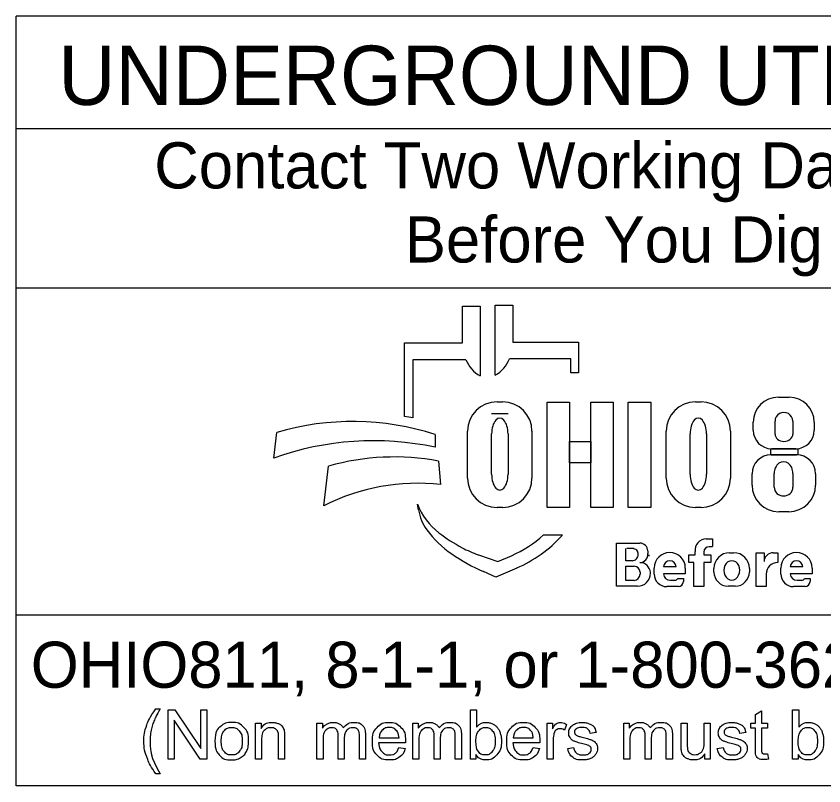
# Model space of a CAD drawing. Extents: x 0 to 34, y 0 to 22.
# Drawn here: x 3.363 to 5.816, y 2.547 to 4.885 of the extents above; entities that cross this region are included whole.
import ezdxf

# ---------------------------------------------------------------- set-up
doc = ezdxf.new("R2010")
doc.units = 0
doc.layers.add('SH_Data', color=7, linetype='Continuous')
doc.layers.add('SH_Text', color=7, linetype='Continuous')

msp = doc.modelspace()

# ---------------------------------------------------------------- linework, layer by layer
at = {"layer": 'SH_Data'}
for p, q in [((3.3626, 2.5473), (3.3626, 4.8848)), ((7.6126, 4.8848), (3.3626, 4.8848)), ((3.3626, 4.5433), (7.6126, 4.5433)), ((3.3626, 4.0599), (7.6126, 4.0599)), ((7.6126, 3.0652), (3.3626, 3.0652)), ((7.6126, 2.5473), (3.3626, 2.5473))]:
    msp.add_line(p, q, dxfattribs=at)
at = {"layer": 'SH_Text'}
for p, q in [((4.7186, 3.8928), (4.7186, 4.0043)), ((4.7186, 4.0043), (4.7723, 4.0043)), ((4.7723, 4.0043), (4.7723, 3.7923)), ((4.8179, 3.7946), (4.8179, 4.0067)), ((4.8179, 4.0067), (4.8716, 4.0067)), ((4.8716, 4.0067), (4.8716, 3.8952)), ((4.5427, 3.669), (4.5427, 3.8928)), ((4.5427, 3.8928), (4.7186, 3.8928)), ((4.8716, 3.8952), (5.0708, 3.8952)), ((5.0708, 3.8952), (5.0708, 3.8014)), ((4.5679, 3.8414), (4.5679, 3.6646)), ((4.729, 3.8414), (4.5679, 3.8414)), ((5.0475, 3.8437), (4.8612, 3.8437)), ((5.0475, 3.8014), (5.0475, 3.8437)), ((5.0708, 3.8014), (5.0475, 3.8014)), ((4.8236, 3.7137), (4.8402, 3.7137)), ((5.4267, 3.7137), (5.4432, 3.7137)), ((5.6782, 3.7277), (5.7109, 3.7277)), ((4.8569, 3.6767), (4.8071, 3.6767)), ((5.6019, 3.6271), (5.6019, 3.6514)), ((5.668, 3.6157), (5.668, 3.655)), ((5.7222, 3.655), (5.7222, 3.6157)), ((5.7872, 3.6514), (5.7872, 3.6271)), ((4.1453, 3.5427), (4.1547, 3.6208)), ((4.636, 3.6143), (4.636, 3.5755)), ((4.7342, 3.4822), (4.7342, 3.6242)), ((4.8071, 3.4936), (4.8071, 3.6159)), ((4.8569, 3.6159), (4.8569, 3.4936)), ((4.9296, 3.6242), (4.9296, 3.4822)), ((5.3372, 3.4822), (5.3372, 3.6242)), ((5.4101, 3.4936), (5.4101, 3.6159)), ((5.4599, 3.6159), (5.4599, 3.4936)), ((5.5327, 3.6242), (5.5327, 3.4822)), ((5.7312, 3.5711), (5.6579, 3.5711)), ((4.6459, 3.5337), (4.6522, 3.4627)), ((5.6561, 3.5527), (5.7334, 3.5527)), ((4.2971, 3.3981), (4.3118, 3.5183)), ((5.5982, 3.4608), (5.5982, 3.4949)), ((5.6657, 3.4549), (5.6657, 3.4958)), ((5.7225, 3.4958), (5.7225, 3.4549)), ((5.7913, 3.4949), (5.7913, 3.4608)), ((4.5848, 3.3852), (4.5818, 3.4031)), ((4.8402, 3.3927), (4.8236, 3.3927)), ((5.4432, 3.3927), (5.4267, 3.3927)), ((5.7103, 3.3799), (5.6791, 3.3799)), ((4.9651, 3.3093), (5.0225, 3.3093)), ((5.459, 3.2971), (5.4784, 3.2971)), ((5.4784, 3.2971), (5.4784, 3.2741)), ((5.1864, 3.1536), (5.1864, 3.2843)), ((5.1864, 3.2843), (5.2576, 3.2843)), ((5.2144, 3.2308), (5.2144, 3.2678)), ((5.2396, 3.2678), (5.2183, 3.2678)), ((5.4784, 3.2736), (5.4683, 3.2736)), ((4.7667, 3.249), (4.8261, 3.2285)), ((4.8261, 3.2285), (4.8671, 3.2463)), ((5.2813, 3.2606), (5.2813, 3.2527)), ((5.4064, 3.2257), (5.4064, 3.2487)), ((5.4064, 3.2487), (5.4257, 3.2487)), ((5.4257, 3.2487), (5.4257, 3.2592)), ((5.4518, 3.2572), (5.4518, 3.2487)), ((5.4518, 3.2487), (5.4734, 3.2487)), ((5.4734, 3.2487), (5.4734, 3.2257)), ((5.5302, 3.2553), (5.5423, 3.2553)), ((5.6105, 3.1524), (5.6105, 3.2551)), ((5.6105, 3.2551), (5.635, 3.2551)), ((5.635, 3.2551), (5.635, 3.2282)), ((5.6623, 3.2551), (5.6761, 3.2551)), ((5.6761, 3.2551), (5.6761, 3.2254)), ((5.2338, 3.2308), (5.2144, 3.2308)), ((5.4213, 3.2257), (5.4064, 3.2257)), ((5.4213, 3.1524), (5.4213, 3.2257)), ((5.4734, 3.2257), (5.4518, 3.2257)), ((5.4518, 3.2257), (5.4518, 3.1524)), ((4.8201, 3.1815), (4.7827, 3.1979)), ((4.8834, 3.2089), (4.8201, 3.1815)), ((5.2144, 3.1714), (5.2144, 3.2143)), ((5.2144, 3.2143), (5.2399, 3.2143)), ((5.258, 3.1962), (5.258, 3.1898)), ((5.2894, 3.1933), (5.2894, 3.1929)), ((5.301, 3.1904), (5.301, 3.2088)), ((5.3675, 3.2128), (5.329, 3.2128)), ((5.3955, 3.1911), (5.3291, 3.1911)), ((5.3955, 3.2088), (5.3955, 3.1911)), ((5.4824, 3.1967), (5.4824, 3.2075)), ((5.5902, 3.2075), (5.5902, 3.1967)), ((5.641, 3.1905), (5.641, 3.1524)), ((5.6859, 3.1904), (5.6859, 3.2088)), ((5.7525, 3.2128), (5.7139, 3.2128)), ((5.7804, 3.1911), (5.714, 3.1911)), ((5.7804, 3.2088), (5.7804, 3.1911)), ((5.2397, 3.1714), (5.2144, 3.1714)), ((5.35, 3.1719), (5.3641, 3.1719)), ((5.3727, 3.1774), (5.3895, 3.1774)), ((5.3895, 3.1774), (5.3895, 3.1676)), ((5.7349, 3.1719), (5.749, 3.1719)), ((5.7576, 3.1774), (5.7745, 3.1774)), ((5.7745, 3.1774), (5.7745, 3.1676)), ((5.2501, 3.1536), (5.1864, 3.1536)), ((5.3743, 3.1524), (5.3389, 3.1524)), ((5.4518, 3.1524), (5.4213, 3.1524)), ((5.5474, 3.1539), (5.5252, 3.1539)), ((5.641, 3.1524), (5.6105, 3.1524)), ((5.7592, 3.1524), (5.7238, 3.1524))]:
    msp.add_line(p, q, dxfattribs=at)
for points in [[(4.9761, 3.7126), (5.044, 3.7126), (5.044, 3.3926), (4.9761, 3.3926)], [(5.1082, 3.7126), (5.1762, 3.7126), (5.1762, 3.3926), (5.1082, 3.3926)], [(5.2215, 3.7126), (5.2903, 3.7126), (5.2903, 3.3926), (5.2215, 3.3926)], [(5.044, 3.5927), (5.1082, 3.5927), (5.1082, 3.5287), (5.044, 3.5287)], [(5.6557, 3.5711), (5.7374, 3.5711), (5.7374, 3.5526), (5.6557, 3.5526)]]:
    msp.add_lwpolyline(points, close=True, dxfattribs=at)
for points in [[(3.7872, 2.7811), (3.8004, 2.7811)], [(3.824, 2.6285), (3.824, 2.7786), (3.8443, 2.7786), (3.9233, 2.6607), (3.9233, 2.7786), (3.9423, 2.7786), (3.9423, 2.6285), (3.922, 2.6285), (3.843, 2.7464), (3.843, 2.6285), (3.824, 2.6285)], [(4.7594, 2.6285), (4.7424, 2.6285), (4.7424, 2.7786), (4.7608, 2.7786), (4.7608, 2.7251)], [(5.6084, 2.6603), (5.6084, 2.723), (5.5947, 2.723), (5.5947, 2.7373), (5.6084, 2.7373), (5.6084, 2.7642), (5.6268, 2.7753), (5.6268, 2.7373), (5.6452, 2.7373), (5.6452, 2.723), (5.6268, 2.723), (5.6268, 2.6592)], [(5.7385, 2.6285), (5.7214, 2.6285), (5.7214, 2.7786), (5.7399, 2.7786), (5.7399, 2.7251)], [(4.0899, 2.6285), (4.0899, 2.7373), (4.1065, 2.7373), (4.1065, 2.7218)], [(4.2763, 2.6285), (4.2763, 2.7373), (4.2928, 2.7373), (4.2928, 2.722)], [(4.5677, 2.6285), (4.5677, 2.7373), (4.5842, 2.7373), (4.5842, 2.722)], [(4.9755, 2.6285), (4.9755, 2.7373), (4.9921, 2.7373), (4.9921, 2.7208)], [(5.0345, 2.7338), (5.0281, 2.7168)], [(5.2087, 2.6285), (5.2087, 2.7373), (5.2252, 2.7373), (5.2252, 2.722)], [(5.383, 2.6699), (5.383, 2.7373), (5.4014, 2.7373), (5.4014, 2.677)], [(5.4527, 2.679), (5.4527, 2.7373), (5.4711, 2.7373), (5.4711, 2.6285), (5.4547, 2.6285)], [(4.4239, 2.7031), (4.4239, 2.6285), (4.4054, 2.6285), (4.4054, 2.697)], [(4.7152, 2.7031), (4.7152, 2.6285), (4.6968, 2.6285), (4.6968, 2.697)], [(5.1245, 2.7092), (5.1064, 2.7068)], [(5.3562, 2.7031), (5.3562, 2.6285), (5.3378, 2.6285), (5.3378, 2.697)], [(5.5791, 2.7092), (5.561, 2.7068)], [(4.1084, 2.6879), (4.1084, 2.6285), (4.0899, 2.6285)], [(4.1783, 2.6954), (4.1783, 2.6285), (4.1599, 2.6285), (4.1599, 2.6946)], [(4.2948, 2.6849), (4.2948, 2.6285), (4.2763, 2.6285)], [(4.3594, 2.6916), (4.3594, 2.6285), (4.341, 2.6285), (4.341, 2.6991)], [(4.5451, 2.6781), (4.4639, 2.6781)], [(4.465, 2.6932), (4.5257, 2.6932)], [(4.5861, 2.6849), (4.5861, 2.6285), (4.5677, 2.6285)], [(4.6508, 2.6916), (4.6508, 2.6285), (4.6324, 2.6285), (4.6324, 2.6991)], [(4.9531, 2.6781), (4.8719, 2.6781)], [(4.8729, 2.6932), (4.9337, 2.6932)], [(4.9939, 2.6855), (4.9939, 2.6285), (4.9755, 2.6285)], [(5.2271, 2.6849), (5.2271, 2.6285), (5.2087, 2.6285)], [(5.2918, 2.6916), (5.2918, 2.6285), (5.2734, 2.6285), (5.2734, 2.6991)], [(4.5255, 2.6636), (4.5446, 2.6612)], [(4.9335, 2.6636), (4.9526, 2.6612)], [(5.0381, 2.661), (5.0563, 2.6638)], [(5.4927, 2.661), (5.5109, 2.6638)], [(4.7594, 2.6421), (4.7594, 2.6285)], [(5.4547, 2.6285), (5.4547, 2.6445)], [(5.6452, 2.6449), (5.6478, 2.6286)], [(5.7385, 2.6421), (5.7385, 2.6285)], [(3.8004, 2.5843), (3.7872, 2.5843)]]:
    msp.add_lwpolyline(points, dxfattribs=at)
for centre, radius, start, end in [((4.8204, 3.8782), 0.0985, 201.9296, 240.7469), ((4.7698, 3.8805), 0.0985, 299.2531, 338.0704), ((4.8236, 3.6242), 0.0895, 90, 180), ((4.8402, 3.6242), 0.0895, 0, 90), ((5.4267, 3.6242), 0.0895, 90, 180), ((5.4432, 3.6242), 0.0895, 0, 90), ((5.6782, 3.6514), 0.0763, 90, 180), ((5.7109, 3.6514), 0.0763, 0, 90), ((4.4145, 2.86), 0.8191, 79.2074, 81.0007), ((4.3848, 2.8347), 0.8191, 72.1402, 106.3144), ((5.6579, 3.6271), 0.056, 180, 270), ((5.7312, 3.6271), 0.056, 270, 0), ((4.4478, 2.7036), 0.8919, 77.8238, 109.8274), ((4.5118, 2.8139), 0.7322, 79.44, 105.8467), ((5.6561, 3.4949), 0.0579, 90, 180), ((5.7334, 3.4949), 0.0579, 0, 90), ((4.5838, 2.8307), 0.6357, 83.8248, 116.8021), ((4.8236, 3.4822), 0.0895, 180, 270), ((4.8402, 3.4822), 0.0895, 270, 0), ((5.4267, 3.4822), 0.0895, 180, 270), ((5.4432, 3.4822), 0.0895, 270, 0), ((5.6791, 3.4608), 0.081, 180, 270), ((5.7103, 3.4608), 0.081, 270, 0), ((4.7692, 3.4753), 0.2008, 201.0457, 232.5314), ((4.7261, 3.4093), 0.1433, 189.6817, 216.0884), ((4.8598, 3.5068), 0.3088, 216.0884, 235.7167), ((4.9617, 3.7265), 0.5173, 232.5314, 241.794), ((4.7237, 3.5768), 0.3602, 293.4582, 312.0712), ((4.7237, 3.5768), 0.401, 293.4582, 317.8286), ((5.459, 3.2636), 0.0335, 90, 187.5187), ((4.8765, 3.5677), 0.3371, 241.794, 250.9821), ((5.2356, 3.2509), 0.0169, 357.8325, 90), ((5.2576, 3.2606), 0.0238, 0, 90), ((5.4683, 3.2572), 0.0165, 90, 180), ((5.0263, 3.751), 0.6044, 235.7167, 246.2325), ((5.2338, 3.2496), 0.0187, 270, 2.0582), ((5.2572, 3.2498), 0.0243, 270, 6.6529), ((5.2678, 3.2484), 0.0175, 347.4023, 0), ((5.3482, 3.2088), 0.0473, 0, 180), ((5.5302, 3.2075), 0.0478, 90, 180), ((5.5423, 3.2075), 0.0478, 0, 90), ((5.6619, 3.2282), 0.0269, 89.2449, 180), ((5.7331, 3.2088), 0.0473, 0, 180), ((5.2573, 3.1934), 0.0321, 4.0748, 90), ((5.3483, 3.2118), 0.0193, 2.9632, 177.0368), ((5.6759, 3.1905), 0.0349, 89.6033, 180), ((5.7332, 3.2118), 0.0193, 2.9632, 177.0368), ((5.2399, 3.1962), 0.0181, 0, 90), ((5.2501, 3.1929), 0.0393, 270, 0), ((5.2564, 3.1933), 0.033, 0, 11.7502), ((5.3389, 3.1904), 0.038, 180, 270), ((5.35, 3.1929), 0.021, 184.827, 270), ((5.5252, 3.1967), 0.0428, 180, 270), ((5.5474, 3.1967), 0.0428, 270, 0), ((5.7238, 3.1904), 0.038, 180, 270), ((5.7349, 3.1929), 0.021, 184.827, 270), ((5.2397, 3.1898), 0.0184, 270, 0), ((5.3641, 3.1813), 0.00938, 270, 335.9979), ((5.3743, 3.1676), 0.0152, 270, 0), ((5.749, 3.1813), 0.00938, 270, 335.9979), ((5.7592, 3.1676), 0.0152, 270, 0)]:
    msp.add_arc(centre, radius, start, end, dxfattribs=at)
for centre, major_axis, ratio, start_param, end_param in [((5.6951, 3.655), (0.0271, 0), 0.969373, 0, 3.141593), ((4.832, 3.6159), (0, 0.0484), 0.514403, 4.712389, 7.853982), ((5.435, 3.6159), (0, 0.0484), 0.514403, 4.712389, 7.853982), ((5.6951, 3.6157), (0.0271, 0), 0.818453, 3.141593, 6.283185), ((5.6941, 3.4958), (0, 0.0358), 0.794529, 4.712389, 7.853982), ((4.832, 3.4936), (0, 0.0484), 0.514403, 1.570796, 4.712389), ((5.435, 3.4936), (0, 0.0484), 0.514403, 1.570796, 4.712389), ((5.6941, 3.4549), (0.0284, 0), 0.959837, 3.141593, 6.283185), ((5.5367, 3.2021), (0, 0.029), 0.832186, 4.712389, 7.853982), ((5.5367, 3.2021), (0, 0.0302), 0.797287, 1.570796, 4.712389)]:
    msp.add_ellipse(centre, major_axis=major_axis, ratio=ratio, start_param=start_param, end_param=end_param, dxfattribs=at)
for points in [[(3.7872, 2.5843), (3.7719, 2.6036), (3.7614, 2.6294), (3.7508, 2.6552), (3.7508, 2.6828), (3.7508, 2.7072), (3.7587, 2.7295), (3.7679, 2.7554), (3.7872, 2.7811)], [(3.8004, 2.7811), (3.788, 2.7598), (3.784, 2.7507), (3.7778, 2.7366), (3.7742, 2.7212), (3.7698, 2.7021), (3.7698, 2.6827), (3.7698, 2.6335), (3.8004, 2.5843)], [(3.9664, 2.6829), (3.9664, 2.7131), (3.9832, 2.7276), (3.9973, 2.7397), (4.0174, 2.7397), (4.0398, 2.7397), (4.0541, 2.725), (4.0683, 2.7103), (4.0683, 2.6844), (4.0683, 2.6634), (4.062, 2.6514), (4.0557, 2.6394), (4.0437, 2.6327), (4.0316, 2.6261), (4.0174, 2.6261), (3.9946, 2.6261), (3.9805, 2.6407), (3.9664, 2.6554), (3.9664, 2.6829)], [(3.9854, 2.6829), (3.9854, 2.662), (3.9945, 2.6516), (4.0036, 2.6412), (4.0174, 2.6412), (4.0311, 2.6412), (4.0402, 2.6516), (4.0493, 2.6621), (4.0493, 2.6835), (4.0493, 2.7037), (4.0402, 2.7141), (4.031, 2.7245), (4.0174, 2.7245), (4.0036, 2.7245), (3.9945, 2.7141), (3.9854, 2.7038), (3.9854, 2.6829)], [(4.1065, 2.7218), (4.1185, 2.7397), (4.1411, 2.7397), (4.1509, 2.7397), (4.1592, 2.7362), (4.1674, 2.7326), (4.1715, 2.7269), (4.1756, 2.7212), (4.1773, 2.7133), (4.1783, 2.7082), (4.1783, 2.6954)], [(4.1599, 2.6946), (4.1599, 2.7059), (4.1577, 2.7115), (4.1556, 2.717), (4.1501, 2.7204), (4.1446, 2.7237), (4.1372, 2.7237), (4.1254, 2.7237), (4.1169, 2.7162), (4.1084, 2.7087), (4.1084, 2.6879)], [(4.2928, 2.722), (4.2979, 2.73), (4.3064, 2.7348), (4.3149, 2.7397), (4.3258, 2.7397), (4.3379, 2.7397), (4.3456, 2.7347), (4.3534, 2.7297), (4.3566, 2.7206), (4.3695, 2.7397), (4.3902, 2.7397), (4.4064, 2.7397), (4.4151, 2.7308), (4.4239, 2.7218), (4.4239, 2.7031)], [(4.341, 2.6991), (4.341, 2.7114), (4.3365, 2.7175), (4.332, 2.7237), (4.3217, 2.7237), (4.3139, 2.7237), (4.3073, 2.7196), (4.3007, 2.7155), (4.2977, 2.7076), (4.2948, 2.6997), (4.2948, 2.6849)], [(4.4054, 2.697), (4.4054, 2.708), (4.4036, 2.7129), (4.4018, 2.7178), (4.3971, 2.7207), (4.3924, 2.7237), (4.3861, 2.7237), (4.3746, 2.7237), (4.367, 2.7161), (4.3594, 2.7084), (4.3594, 2.6916)], [(4.5446, 2.6612), (4.5401, 2.6445), (4.5279, 2.6353), (4.5157, 2.6261), (4.4967, 2.6261), (4.4729, 2.6261), (4.4589, 2.6408), (4.4449, 2.6555), (4.4449, 2.682), (4.4449, 2.7094), (4.4591, 2.7246), (4.4732, 2.7397), (4.4957, 2.7397), (4.5175, 2.7397), (4.5314, 2.7249), (4.5452, 2.71), (4.5452, 2.6831), (4.5452, 2.6814), (4.5451, 2.6781)], [(4.5257, 2.6932), (4.5245, 2.707), (4.5188, 2.7139), (4.5099, 2.7246), (4.4959, 2.7246), (4.4832, 2.7246), (4.4745, 2.7161), (4.4659, 2.7075), (4.465, 2.6932)], [(4.5842, 2.722), (4.5893, 2.73), (4.5978, 2.7348), (4.6063, 2.7397), (4.6172, 2.7397), (4.6293, 2.7397), (4.637, 2.7347), (4.6447, 2.7297), (4.6479, 2.7206), (4.6609, 2.7397), (4.6816, 2.7397), (4.6978, 2.7397), (4.7065, 2.7308), (4.7152, 2.7218), (4.7152, 2.7031)], [(4.6324, 2.6991), (4.6324, 2.7114), (4.6279, 2.7175), (4.6233, 2.7237), (4.6131, 2.7237), (4.6053, 2.7237), (4.5987, 2.7196), (4.5921, 2.7155), (4.5891, 2.7076), (4.5861, 2.6997), (4.5861, 2.6849)], [(4.6968, 2.697), (4.6968, 2.708), (4.695, 2.7129), (4.6932, 2.7178), (4.6885, 2.7207), (4.6838, 2.7237), (4.6774, 2.7237), (4.666, 2.7237), (4.6584, 2.7161), (4.6508, 2.7084), (4.6508, 2.6916)], [(4.7592, 2.6837), (4.7592, 2.6641), (4.7645, 2.6554), (4.7732, 2.6412), (4.788, 2.6412), (4.8001, 2.6412), (4.8089, 2.6517), (4.8177, 2.6622), (4.8177, 2.683), (4.8177, 2.7043), (4.8092, 2.7145), (4.8008, 2.7246), (4.7888, 2.7246), (4.7768, 2.7246), (4.768, 2.7141), (4.7592, 2.7036), (4.7592, 2.6837)], [(4.7608, 2.7251), (4.7725, 2.7397), (4.7906, 2.7397), (4.8006, 2.7397), (4.8096, 2.7357), (4.8185, 2.7316), (4.8243, 2.7243), (4.8301, 2.717), (4.8334, 2.7066), (4.8367, 2.6963), (4.8367, 2.6845), (4.8367, 2.6566), (4.8228, 2.6413), (4.809, 2.6261), (4.7896, 2.6261), (4.7704, 2.6261), (4.7594, 2.6421)], [(4.9526, 2.6612), (4.9481, 2.6445), (4.9359, 2.6353), (4.9237, 2.6261), (4.9047, 2.6261), (4.8809, 2.6261), (4.8669, 2.6408), (4.8529, 2.6555), (4.8529, 2.682), (4.8529, 2.7094), (4.8671, 2.7246), (4.8812, 2.7397), (4.9037, 2.7397), (4.9255, 2.7397), (4.9393, 2.7249), (4.9532, 2.71), (4.9532, 2.6831), (4.9532, 2.6814), (4.9531, 2.6781)], [(4.9337, 2.6932), (4.9325, 2.707), (4.9267, 2.7139), (4.9179, 2.7246), (4.9039, 2.7246), (4.8912, 2.7246), (4.8825, 2.7161), (4.8739, 2.7075), (4.8729, 2.6932)], [(4.9921, 2.7208), (4.9984, 2.7324), (5.0038, 2.736), (5.0092, 2.7397), (5.0156, 2.7397), (5.0249, 2.7397), (5.0345, 2.7338)], [(5.1064, 2.7068), (5.1052, 2.7152), (5.0993, 2.7199), (5.0934, 2.7246), (5.0826, 2.7246), (5.0699, 2.7246), (5.0645, 2.7204), (5.059, 2.7162), (5.059, 2.7105), (5.059, 2.707), (5.0613, 2.7041), (5.0635, 2.7011), (5.0684, 2.6992), (5.0711, 2.6981), (5.0847, 2.6944), (5.1043, 2.6892), (5.112, 2.6859), (5.1198, 2.6826), (5.1242, 2.6762), (5.1286, 2.6699), (5.1286, 2.6605), (5.1286, 2.6512), (5.1232, 2.6431), (5.1178, 2.635), (5.1077, 2.6305), (5.0975, 2.6261), (5.0847, 2.6261), (5.0634, 2.6261), (5.0523, 2.6349), (5.0412, 2.6437), (5.0381, 2.661)], [(5.0563, 2.6638), (5.0578, 2.6529), (5.0649, 2.647), (5.0719, 2.6412), (5.0845, 2.6412), (5.0973, 2.6412), (5.1035, 2.6464), (5.1096, 2.6515), (5.1096, 2.6585), (5.1096, 2.6648), (5.1042, 2.6684), (5.1004, 2.6708), (5.0853, 2.6746), (5.065, 2.6797), (5.0571, 2.6835), (5.0493, 2.6872), (5.0452, 2.6938), (5.0412, 2.7004), (5.0412, 2.7084), (5.0412, 2.7157), (5.0445, 2.7219), (5.0479, 2.728), (5.0536, 2.7321), (5.0579, 2.7353), (5.0653, 2.7375), (5.0728, 2.7397), (5.0813, 2.7397), (5.0941, 2.7397), (5.1038, 2.736), (5.1135, 2.7323), (5.1181, 2.726), (5.1228, 2.7197), (5.1245, 2.7092)], [(5.2252, 2.722), (5.2303, 2.73), (5.2388, 2.7348), (5.2473, 2.7397), (5.2582, 2.7397), (5.2703, 2.7397), (5.278, 2.7347), (5.2857, 2.7297), (5.2889, 2.7206), (5.3019, 2.7397), (5.3226, 2.7397), (5.3388, 2.7397), (5.3475, 2.7308), (5.3562, 2.7218), (5.3562, 2.7031)], [(5.2734, 2.6991), (5.2734, 2.7114), (5.2689, 2.7175), (5.2643, 2.7237), (5.2541, 2.7237), (5.2463, 2.7237), (5.2397, 2.7196), (5.2331, 2.7155), (5.2301, 2.7076), (5.2271, 2.6997), (5.2271, 2.6849)], [(5.3378, 2.697), (5.3378, 2.708), (5.336, 2.7129), (5.3342, 2.7178), (5.3295, 2.7207), (5.3248, 2.7237), (5.3184, 2.7237), (5.307, 2.7237), (5.2994, 2.7161), (5.2918, 2.7084), (5.2918, 2.6916)], [(5.561, 2.7068), (5.5598, 2.7152), (5.5539, 2.7199), (5.548, 2.7246), (5.5372, 2.7246), (5.5245, 2.7246), (5.519, 2.7204), (5.5136, 2.7162), (5.5136, 2.7105), (5.5136, 2.707), (5.5159, 2.7041), (5.5181, 2.7011), (5.5229, 2.6992), (5.5257, 2.6981), (5.5392, 2.6944), (5.5588, 2.6892), (5.5666, 2.6859), (5.5743, 2.6826), (5.5788, 2.6762), (5.5832, 2.6699), (5.5832, 2.6605), (5.5832, 2.6512), (5.5778, 2.6431), (5.5724, 2.635), (5.5622, 2.6305), (5.5521, 2.6261), (5.5393, 2.6261), (5.518, 2.6261), (5.5069, 2.6349), (5.4957, 2.6437), (5.4927, 2.661)], [(5.5109, 2.6638), (5.5124, 2.6529), (5.5194, 2.647), (5.5265, 2.6412), (5.5391, 2.6412), (5.5519, 2.6412), (5.558, 2.6464), (5.5642, 2.6515), (5.5642, 2.6585), (5.5642, 2.6648), (5.5587, 2.6684), (5.5549, 2.6708), (5.5399, 2.6746), (5.5196, 2.6797), (5.5117, 2.6835), (5.5039, 2.6872), (5.4998, 2.6938), (5.4958, 2.7004), (5.4958, 2.7084), (5.4958, 2.7157), (5.4991, 2.7219), (5.5024, 2.728), (5.5082, 2.7321), (5.5125, 2.7353), (5.5199, 2.7375), (5.5274, 2.7397), (5.5359, 2.7397), (5.5487, 2.7397), (5.5584, 2.736), (5.5681, 2.7323), (5.5727, 2.726), (5.5773, 2.7197), (5.5791, 2.7092)], [(5.7383, 2.6837), (5.7383, 2.6641), (5.7436, 2.6554), (5.7523, 2.6412), (5.7671, 2.6412), (5.7792, 2.6412), (5.7879, 2.6517), (5.7967, 2.6622), (5.7967, 2.683), (5.7967, 2.7043), (5.7883, 2.7145), (5.7799, 2.7246), (5.7679, 2.7246), (5.7558, 2.7246), (5.747, 2.7141), (5.7383, 2.7036), (5.7383, 2.6837)], [(5.7399, 2.7251), (5.7515, 2.7397), (5.7697, 2.7397), (5.7797, 2.7397), (5.7887, 2.7357), (5.7976, 2.7316), (5.8034, 2.7243), (5.8092, 2.717), (5.8125, 2.7066), (5.8157, 2.6963), (5.8157, 2.6845), (5.8157, 2.6566), (5.8019, 2.6413), (5.7881, 2.6261), (5.7687, 2.6261), (5.7494, 2.6261), (5.7385, 2.6421)], [(5.0281, 2.7168), (5.0214, 2.7207), (5.0146, 2.7207), (5.0086, 2.7207), (5.0038, 2.7171), (4.999, 2.7134), (4.997, 2.707), (4.9939, 2.6971), (4.9939, 2.6855)], [(4.4639, 2.6781), (4.465, 2.6602), (4.4741, 2.6507), (4.4832, 2.6412), (4.4968, 2.6412), (4.507, 2.6412), (4.5141, 2.6465), (4.5213, 2.6519), (4.5255, 2.6636)], [(4.8719, 2.6781), (4.8729, 2.6602), (4.8821, 2.6507), (4.8912, 2.6412), (4.9048, 2.6412), (4.915, 2.6412), (4.9221, 2.6465), (4.9293, 2.6519), (4.9335, 2.6636)], [(5.4014, 2.677), (5.4014, 2.6626), (5.4026, 2.6575), (5.4043, 2.6503), (5.4099, 2.6461), (5.4156, 2.642), (5.4239, 2.642), (5.4322, 2.642), (5.4394, 2.6462), (5.4467, 2.6505), (5.4497, 2.6578), (5.4527, 2.6651), (5.4527, 2.679)], [(5.4547, 2.6445), (5.442, 2.6261), (5.4202, 2.6261), (5.4106, 2.6261), (5.4022, 2.6298), (5.3939, 2.6334), (5.3898, 2.639), (5.3858, 2.6446), (5.3842, 2.6527), (5.383, 2.6581), (5.383, 2.6699)], [(5.6478, 2.6286), (5.6401, 2.627), (5.6339, 2.627), (5.6239, 2.627), (5.6184, 2.6302), (5.6129, 2.6333), (5.6106, 2.6385), (5.6084, 2.6437), (5.6084, 2.6603)], [(5.6268, 2.6592), (5.6268, 2.6513), (5.6278, 2.6491), (5.6287, 2.6468), (5.6309, 2.6455), (5.6331, 2.6442), (5.6372, 2.6442), (5.6402, 2.6442), (5.6452, 2.6449)]]:
    msp.add_open_spline(points, degree=3, dxfattribs=at)

# ---------------------------------------------------------------- texts
for s, height, p in [('UNDERGROUND UTILITIES', 0.18, (3.4908, 4.6152)), ('Contact Two Working Days', 0.14, (3.7822, 4.3617)), ('Before You Dig', 0.14, (4.5434, 4.1367)), ('OHIO811, 8-1-1, or 1-800-362-2764', 0.14, (3.4071, 2.8452))]:
    msp.add_text(s, height=height, dxfattribs=at).set_placement(p)

doc.saveas('drawing.dxf')
